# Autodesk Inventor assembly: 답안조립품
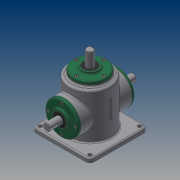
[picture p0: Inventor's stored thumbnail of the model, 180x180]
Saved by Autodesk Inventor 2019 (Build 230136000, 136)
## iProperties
Created: 2019-03
Part Number: 답안조립품
Material: 일반
Document SubType Name: Assembly
Designer: PC312-13
Author: PC312-13
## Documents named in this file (16)
- C:\Users\PC312-13\Desktop\490314V1001\답안조립품.iam
- C:\Users\PC312-13\Desktop\490314V1001\본체.ipt
- C:\Users\PC312-13\Desktop\490314V1001\커버.ipt
- C:\Users\PC312-13\Desktop\490314V1001\오일 실.ipt
- 오일 실.ipt
- C:\Users\PC312-13\Desktop\490314V1001\볼트 M4.ipt
- 볼트 M4.ipt
- C:\Users\PC312-13\Desktop\490314V1001\메인 축.ipt
- 메인 축.ipt
- C:\Users\PC312-13\Desktop\490314V1001\베어링 6203.ipt
- C:\Users\PC312-13\Desktop\490314V1001\서브 축.ipt
- 서브 축.ipt
- C:\Users\PC312-13\Desktop\490314V1001\키 5x5.ipt
- C:\Users\PC312-13\Desktop\490314V1001\키 4x4.ipt
- C:\Users\PC312-13\Desktop\490314V1001\메인 베벨기어.ipt
- C:\Users\PC312-13\Desktop\490314V1001\서브 베벨기어.ipt
